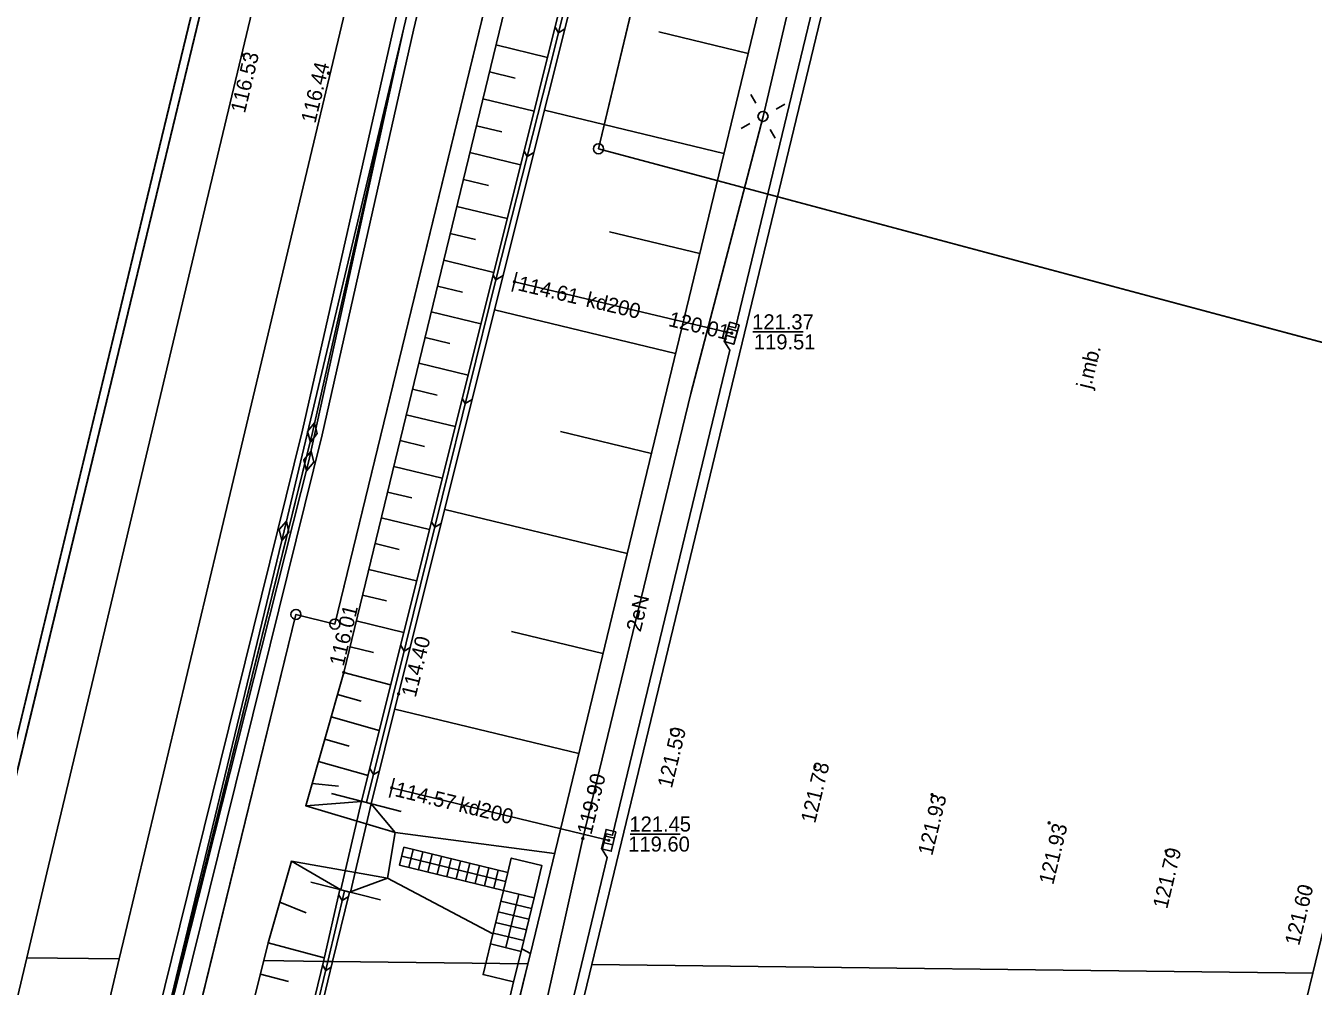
# Model space of a CAD drawing. Extents: x 6424617 to 6425697, y 5665845 to 5667190.
# Drawn here: x 6425319.6 to 6425383.8, y 5666563.1 to 5666611 of the extents above; entities that cross this region are included whole.
import ezdxf

# ---------------------------------------------------------------- set-up
doc = ezdxf.new("R2010")
doc.units = 0
for name, color, linetype in [('Warstwa 1', 7, 'Continuous'), ('Warstwa 10', 7, 'Continuous'), ('Warstwa 12', 7, 'Continuous'), ('Warstwa 13', 7, 'Continuous'), ('Warstwa 14', 7, 'Continuous'), ('Warstwa 15', 7, 'Continuous'), ('Warstwa 19', 7, 'Continuous'), ('Warstwa 2', 7, 'Continuous'), ('Warstwa 20', 7, 'Continuous'), ('Warstwa 21', 7, 'Continuous'), ('Warstwa 22', 7, 'Continuous'), ('Warstwa 25', 7, 'Continuous'), ('Warstwa 4', 7, 'Continuous'), ('Warstwa 47', 7, 'Continuous'), ('Warstwa 6', 7, 'Continuous'), ('Warstwa 61', 7, 'Continuous'), ('Warstwa 7', 7, 'Continuous'), ('Warstwa 8', 7, 'Continuous'), ('Warstwa 9', 7, 'Continuous')]:
    doc.layers.add(name, color=color, linetype=linetype)

msp = doc.modelspace()

# ---------------------------------------------------------------- linework, layer by layer
at = {"layer": 'Warstwa 1'}
for p, q in [((6425335.03, 5666581.17), (6425379.44, 5666763.67)), ((6425335.03, 5666581.17), (6425379.44, 5666763.67)), ((6425313.029, 5666550.146), (6425358.794, 5666739.45)), ((6425313.029, 5666550.146), (6425358.794, 5666739.45)), ((6425348.172, 5666604.865), (6425360.791, 5666657.874)), ((6425348.172, 5666604.865), (6425360.791, 5666657.874)), ((6425348.172, 5666604.865), (6425407.267, 5666589.052)), ((6425348.172, 5666604.865), (6425407.267, 5666589.052)), ((6425294.11, 5666422.45), (6425333.09, 5666581.65)), ((6425294.11, 5666422.45), (6425333.09, 5666581.65)), ((6425333.09, 5666581.65), (6425335.03, 5666581.17)), ((6425333.09, 5666581.65), (6425335.03, 5666581.17))]:
    msp.add_line(p, q, dxfattribs=at)
at = {"layer": 'Warstwa 10'}
for points in [[(6425353.93, 5666675.12), (6425353.26, 5666673.06), (6425338.47, 5666610.89)], [(6425338.47, 5666610.89), (6425332.5, 5666585.82)], [(6425338.47, 5666610.89), (6425333.91, 5666590.72)], [(6425333.91, 5666590.72), (6425327.399, 5666564.443)], [(6425332.5, 5666585.82), (6425327.338, 5666564.444)], [(6425334.86, 5666572.73), (6425338.33, 5666571.83)], [(6425333.83, 5666568.3), (6425337.3, 5666567.42)], [(6425327.338, 5666564.444), (6425324.99, 5666554.72), (6425317.35, 5666522.26), (6425310.45, 5666493.89), (6425307.494, 5666481.767)], [(6425327.447, 5666564.443), (6425324.99, 5666554.72)], [(6425324.99, 5666554.72), (6425327.399, 5666564.443)]]:
    msp.add_lwpolyline(points, dxfattribs=at)
for centre in [(6425348.172, 5666604.865), (6425333.09, 5666581.65), (6425335.03, 5666581.17)]:
    msp.add_circle(centre, 0.25, dxfattribs=at)
at = {"layer": 'Warstwa 12'}
for points in [[(6425371.5, 5666668.86), (6425368.61, 5666657.14), (6425364.68, 5666640.79), (6425360.52, 5666624.1), (6425356.37, 5666606.48), (6425352.78, 5666592.67), (6425347.39, 5666570.48), (6425345.993, 5666564.219)], [(6425343.98, 5666598.23), (6425354.56, 5666595.72), (6425354.81, 5666595.67)], [(6425337.87, 5666573.01), (6425348.44, 5666570.45), (6425348.68, 5666570.39)], [(6425339.14, 5666535.23), (6425344.13, 5666555.87), (6425345.993, 5666564.219)]]:
    msp.add_lwpolyline(points, dxfattribs=at)
at = {"layer": 'Warstwa 14'}
for p, q in [((6425358.364, 5666595.738), (6425355.863, 5666595.738)), ((6425352.245, 5666570.704), (6425349.744, 5666570.704))]:
    msp.add_line(p, q, dxfattribs=at)
for centre in [(6425343.98, 5666598.23), (6425354.56, 5666595.72), (6425354.81, 5666595.67), (6425337.87, 5666573.01), (6425347.39, 5666570.48), (6425348.68, 5666570.39)]:
    msp.add_circle(centre, 0.045, dxfattribs=at)
at = {"layer": 'Warstwa 19'}
for points in [[(6425333.808, 5666590.231), (6425334.155, 5666590.669), (6425334.012, 5666591.209), (6425333.665, 5666590.771)], [(6425333.609, 5666588.815), (6425333.973, 5666589.239), (6425333.851, 5666589.785), (6425333.487, 5666589.361)], [(6425332.378, 5666585.335), (6425332.742, 5666585.759), (6425332.622, 5666586.305), (6425332.258, 5666585.881)]]:
    msp.add_lwpolyline(points, close=True, dxfattribs=at)
at = {"layer": 'Warstwa 2'}
for points in [[(6425351.541, 5666814.161), (6425346.19, 5666783.6), (6425359.15, 5666739.31), (6425316.945, 5666564.569)], [(6425344.106, 5666562.008), (6425343.653, 5666562.12), (6425343.94, 5666563.332)]]:
    msp.add_lwpolyline(points, dxfattribs=at)
msp.add_circle((6425356.37, 5666606.48), 0.25, dxfattribs=at)
at = {"layer": 'Warstwa 20'}
for points in [[(6425404.522, 5666813.522), (6425404.196, 5666811.714), (6425403.132, 5666806.373), (6425401.821, 5666800.594), (6425391.249, 5666756.921), (6425390.59, 5666754.182), (6425344.776, 5666564.747), (6425344.652, 5666564.235)], [(6425338.043, 5666570.781), (6425333.575, 5666572.112), (6425335.476, 5666578.76), (6425340.458, 5666599.306), (6425345.009, 5666618.09), (6425349.685, 5666637.202), (6425354.713, 5666657.518), (6425359.407, 5666676.499), (6425364.317, 5666696.337), (6425370.582, 5666721.422), (6425376.359, 5666746.636), (6425378.933, 5666757.904), (6425380.111, 5666761.653), (6425384.025, 5666760.723)], [(6425331.487, 5666564.394), (6425331.711, 5666565.283), (6425332.875, 5666569.344), (6425337.651, 5666568.507)], [(6425306.496, 5666399.029), (6425311.317, 5666419.144), (6425338.808, 5666540.067), (6425344.652, 5666564.235)], [(6425307.315, 5666466.947), (6425307.814, 5666468.883), (6425314.453, 5666496.422), (6425321.245, 5666524.099), (6425327.788, 5666549.679), (6425331.487, 5666564.394)]]:
    msp.add_lwpolyline(points, dxfattribs=at)
at = {"layer": 'Warstwa 21'}
for p, q in [((6425344.095, 5666598.717), (6425343.865, 5666597.743)), ((6425337.988, 5666573.496), (6425337.752, 5666572.524))]:
    msp.add_line(p, q, dxfattribs=at)
for points in [[(6425334.917, 5666564.352), (6425335.752, 5666567.813), (6425337.651, 5666568.507), (6425338.043, 5666570.781), (6425336.841, 5666572.216), (6425338.207, 5666577.69), (6425353.108, 5666637.3), (6425362.223, 5666676.199), (6425366.904, 5666695.59), (6425372.943, 5666720.9), (6425378.889, 5666746.05), (6425381.38, 5666757.139), (6425382.211, 5666759.415), (6425384.025, 5666760.723), (6425384.533, 5666762.234), (6425383.43, 5666764.314), (6425384.167, 5666768.022), (6425388.16, 5666783.635), (6425394.548, 5666811.629), (6425394.925, 5666813.637)], [(6425382.211, 5666759.415), (6425381.594, 5666759.566), (6425380.892, 5666757.278), (6425378.411, 5666746.159), (6425372.465, 5666721.008), (6425366.426, 5666695.699), (6425361.745, 5666676.307), (6425352.63, 5666637.429), (6425337.729, 5666577.819), (6425336.364, 5666572.34), (6425336.841, 5666572.216)], [(6425335.752, 5666567.813), (6425335.269, 5666567.935), (6425334.457, 5666564.358)], [(6425307.108, 5666449.766), (6425311.778, 5666468.481), (6425334.917, 5666564.352)], [(6425334.457, 5666564.358), (6425324.684, 5666524.027), (6425311.3, 5666468.61), (6425307.134, 5666451.915)]]:
    msp.add_lwpolyline(points, dxfattribs=at)
at = {"layer": 'Warstwa 22'}
msp.add_lwpolyline([(6425336.356, 5666572.342), (6425336.839, 5666572.217), (6425335.805, 5666567.799), (6425335.321, 5666567.922)], close=True, dxfattribs=at)
at = {"layer": 'Warstwa 25'}
for centre in [(6425330.459, 5666609.53), (6425334.715, 5666608.633), (6425335.476, 5666578.76), (6425338.207, 5666577.69), (6425351.799, 5666575.894), (6425358.959, 5666574.074), (6425364.795, 5666572.668), (6425370.632, 5666571.263), (6425376.458, 5666569.847), (6425383.537, 5666568.018)]:
    msp.add_circle(centre, 0.045, dxfattribs=at)
at = {"layer": 'Warstwa 4'}
for p, q in [((6425355.002, 5666595.433), (6425354.521, 5666595.571)), ((6425355.099, 5666595.769), (6425354.618, 5666595.907)), ((6425348.963, 5666570.503), (6425348.477, 5666570.618)), ((6425348.883, 5666570.162), (6425348.397, 5666570.277))]:
    msp.add_line(p, q, dxfattribs=at)
for points in [[(6425356.007, 5666607.136), (6425355.765, 5666607.574)], [(6425357.026, 5666606.843), (6425357.464, 5666607.085)], [(6425355.714, 5666606.117), (6425355.276, 5666605.875)], [(6425356.733, 5666605.824), (6425356.975, 5666605.386)]]:
    msp.add_lwpolyline(points, dxfattribs=at)
for points in [[(6425355.189, 5666596.081), (6425354.912, 5666595.12), (6425354.431, 5666595.259), (6425354.708, 5666596.22)], [(6425349.038, 5666570.819), (6425348.809, 5666569.846), (6425348.322, 5666569.961), (6425348.551, 5666570.934)]]:
    msp.add_lwpolyline(points, close=True, dxfattribs=at)
at = {"layer": 'Warstwa 47'}
for points in [[(6425404.522, 5666813.522), (6425404.196, 5666811.714), (6425403.132, 5666806.373), (6425401.821, 5666800.594), (6425391.249, 5666756.921), (6425390.59, 5666754.182), (6425344.776, 5666564.747), (6425344.652, 5666564.235)], [(6425344.651, 5666564.235), (6425344.106, 5666562.008), (6425311.317, 5666419.144), (6425306.496, 5666399.029)]]:
    msp.add_lwpolyline(points, dxfattribs=at)
at = {"layer": 'Warstwa 6'}
for points in [[(6425358.794, 5666739.45), (6425345.837, 5666783.728), (6425348.185, 5666793.45), (6425355.292, 5666837.846), (6425290.369, 5666852.842), (6425257.3, 5666717.295), (6425256.529, 5666713.915), (6425237.206, 5666634.214), (6425213.474, 5666536.345), (6425279.567, 5666529.498), (6425296.119, 5666527.878), (6425306.817, 5666551.711), (6425313.029, 5666550.146)], [(6425360.791, 5666657.874), (6425348.172, 5666604.865), (6425407.267, 5666589.052), (6425420.309, 5666643.115)]]:
    msp.add_lwpolyline(points, close=True, dxfattribs=at)
for points in [[(6425244.275, 5666264.977), (6425279.037, 5666410.906), (6425312.219, 5666546.795), (6425313.029, 5666550.146), (6425358.794, 5666739.45), (6425345.837, 5666783.728), (6425348.185, 5666793.45), (6425355.292, 5666837.846), (6425351.457, 5666842.463), (6425355.995, 5666841.398), (6425356.96, 5666840.82), (6425392.62, 5666819.33), (6425392.36, 5666816.84), (6425379.44, 5666763.67), (6425335.03, 5666581.17), (6425333.09, 5666581.65), (6425294.11, 5666422.45), (6425272.8, 5666335.34)], [(6425353.441, 5666367.596), (6425363.818, 5666408.694), (6425377.52, 5666465.123), (6425381.456, 5666483.847), (6425392.009, 5666527.133), (6425393.198, 5666530.378), (6425400.851, 5666561.248), (6425407.267, 5666589.052), (6425348.172, 5666604.865), (6425360.791, 5666657.874), (6425420.309, 5666643.115), (6425424.332, 5666659.157), (6425447.915, 5666756.464), (6425449.817, 5666764.101), (6425450.35, 5666766.844), (6425453.13, 5666778.441), (6425454.155, 5666782.149), (6425437.407, 5666792.342), (6425392.62, 5666819.33)], [(6425392.36, 5666816.84), (6425379.44, 5666763.67), (6425335.03, 5666581.17), (6425333.09, 5666581.65), (6425294.11, 5666422.45), (6425272.8, 5666335.34)], [(6425347.315, 5666564.203), (6425348.603, 5666569.53), (6425348.351, 5666569.934), (6425348.545, 5666570.721), (6425348.874, 5666570.645), (6425354.722, 5666594.817), (6425354.469, 5666595.222), (6425354.653, 5666596.019), (6425354.992, 5666595.933), (6425359.424, 5666614.259)], [(6425306.368, 5666388.415), (6425311.528, 5666409.747), (6425311.275, 5666410.152), (6425311.459, 5666410.938), (6425311.798, 5666410.862), (6425324.365, 5666464.253), (6425324.113, 5666464.668), (6425324.297, 5666465.454), (6425324.626, 5666465.379), (6425330.531, 5666491.58), (6425330.278, 5666491.995), (6425330.472, 5666492.782), (6425330.801, 5666492.706), (6425336.716, 5666518.898), (6425336.453, 5666519.323), (6425336.638, 5666520.11), (6425336.966, 5666520.034), (6425342.505, 5666544.261), (6425342.253, 5666544.676), (6425342.437, 5666545.463), (6425342.766, 5666545.387), (6425347.315, 5666564.203)]]:
    msp.add_lwpolyline(points, dxfattribs=at)
at = {"layer": 'Warstwa 61'}
for points in [[(6425365.002, 5666813.999), (6425364.967, 5666813.872), (6425361.084, 5666799.763), (6425361.077, 5666799.738), (6425357.8, 5666784.86), (6425359.44, 5666776.98), (6425364.19, 5666763.93), (6425367.97, 5666751.39), (6425368.86, 5666745.46), (6425368.53, 5666739.28), (6425366.74, 5666730.22), (6425362.21, 5666711.06), (6425358.59, 5666696.28), (6425353.93, 5666675.12), (6425353.26, 5666673.06), (6425338.47, 5666610.89), (6425333.911, 5666590.725), (6425333.909, 5666590.715), (6425327.427, 5666564.557), (6425327.399, 5666564.443)], [(6425338.361, 5666569.595), (6425343.54, 5666568.341)], [(6425344.195, 5666567.708), (6425343.552, 5666565.04)], [(6425327.399, 5666564.443), (6425307.494, 5666481.768)]]:
    msp.add_lwpolyline(points, dxfattribs=at)
at = {"layer": 'Warstwa 7'}
for points in [[(6425338.469, 5666570.043), (6425343.648, 5666568.789), (6425343.821, 5666569.506), (6425345.345, 5666569.138), (6425344.958, 5666567.524), (6425343.432, 5666567.892), (6425338.253, 5666569.146)], [(6425343.432, 5666567.892), (6425342.785, 5666565.225), (6425342.416, 5666563.699), (6425343.94, 5666563.332), (6425344.318, 5666564.855), (6425344.958, 5666567.524)]]:
    msp.add_lwpolyline(points, close=True, dxfattribs=at)
for points in [[(6425338.94, 5666569.929), (6425338.724, 5666569.032)], [(6425339.411, 5666569.815), (6425339.195, 5666568.918)], [(6425339.881, 5666569.701), (6425339.665, 5666568.804)], [(6425340.352, 5666569.587), (6425340.136, 5666568.69)], [(6425340.823, 5666569.473), (6425340.607, 5666568.576)], [(6425341.294, 5666569.359), (6425341.078, 5666568.462)], [(6425341.765, 5666569.245), (6425341.549, 5666568.348)], [(6425342.236, 5666569.131), (6425342.02, 5666568.234)], [(6425342.706, 5666569.017), (6425342.49, 5666568.12)], [(6425343.177, 5666568.903), (6425342.961, 5666568.006)], [(6425343.648, 5666568.789), (6425343.432, 5666567.892)], [(6425343.303, 5666567.359), (6425344.83, 5666566.99)], [(6425343.173, 5666566.825), (6425344.702, 5666566.456)], [(6425343.044, 5666566.292), (6425344.574, 5666565.923)], [(6425342.785, 5666565.225), (6425344.318, 5666564.855)], [(6425342.914, 5666565.758), (6425344.446, 5666565.389)]]:
    msp.add_lwpolyline(points, dxfattribs=at)
at = {"layer": 'Warstwa 8'}
for p, q in [((6425347.831, 5666564.197), (6425400.917, 5666783.785)), ((6425383.772, 5666563.763), (6425403.546, 5666645.693)), ((6425328.55, 5666601.862), (6425331.332, 5666613.536)), ((6425332.933, 5666600.813), (6425335.715, 5666612.486)), ((6425325.314, 5666588.236), (6425328.55, 5666601.862)), ((6425329.231, 5666585.244), (6425332.933, 5666600.813)), ((6425322.997, 5666578.505), (6425325.314, 5666588.236)), ((6425324.598, 5666565.792), (6425329.231, 5666585.244)), ((6425320.681, 5666568.773), (6425322.997, 5666578.505)), ((6425319.672, 5666564.536), (6425320.681, 5666568.773)), ((6425324.286, 5666564.481), (6425324.598, 5666565.792)), ((6425316.719, 5666552.14), (6425319.672, 5666564.536)), ((6425319.672, 5666564.536), (6425324.286, 5666564.481)), ((6425319.672, 5666564.536), (6425324.286, 5666564.481)), ((6425319.965, 5666546.329), (6425324.286, 5666564.481)), ((6425342.162, 5666540.747), (6425347.831, 5666564.197)), ((6425347.831, 5666564.197), (6425383.772, 5666563.763)), ((6425347.831, 5666564.197), (6425383.772, 5666563.763)), ((6425377.625, 5666538.377), (6425383.772, 5666563.763))]:
    msp.add_line(p, q, dxfattribs=at)
for points in [[(6425365.519, 5666813.992), (6425364.485, 5666814.005), (6425360.594, 5666799.87), (6425357.289, 5666784.863), (6425358.958, 5666776.843), (6425363.715, 5666763.772), (6425367.481, 5666751.28), (6425368.358, 5666745.436), (6425368.033, 5666739.342), (6425366.251, 5666730.326), (6425361.724, 5666711.177), (6425358.103, 5666696.393), (6425353.447, 5666675.251), (6425352.778, 5666673.195), (6425337.983, 5666611.003), (6425333.423, 5666590.835), (6425326.886, 5666564.449)], [(6425327.912, 5666564.437), (6425334.397, 5666590.605), (6425338.957, 5666610.777), (6425353.742, 5666672.925), (6425354.413, 5666674.989), (6425359.077, 5666696.167), (6425362.696, 5666710.943), (6425367.229, 5666730.114), (6425369.027, 5666739.218), (6425369.362, 5666745.484), (6425368.459, 5666751.5), (6425364.665, 5666764.088), (6425359.922, 5666777.117), (6425358.311, 5666784.857), (6425361.566, 5666799.63), (6425365.519, 5666813.992)], [(6425338.47, 5666610.89), (6425333.73, 5666589.3)], [(6425333.73, 5666589.3), (6425327.447, 5666564.443)], [(6425307.467, 5666479.546), (6425310.936, 5666493.772), (6425317.836, 5666522.144), (6425325.476, 5666554.603), (6425327.912, 5666564.437)], [(6425307.521, 5666483.988), (6425309.964, 5666494.008), (6425316.864, 5666522.376), (6425324.504, 5666554.837), (6425326.886, 5666564.449)]]:
    msp.add_lwpolyline(points, dxfattribs=at)
at = {"layer": 'Warstwa 9'}
for p, q in [((6425316.945, 5666564.569), (6425359.15, 5666739.31)), ((6425345.664, 5666608.594), (6425348.2, 5666618.817)), ((6425346.004, 5666610.923), (6425346.172, 5666610.644)), ((6425346.493, 5666610.838), (6425346.172, 5666610.644)), ((6425355.626, 5666609.613), (6425351.176, 5666610.69)), ((6425343.059, 5666610.04), (6425345.628, 5666609.419)), ((6425342.734, 5666608.698), (6425344.013, 5666608.388)), ((6425343.07, 5666598.39), (6425345.664, 5666608.594)), ((6425342.408, 5666607.356), (6425344.958, 5666606.739)), ((6425354.421, 5666604.628), (6425345.481, 5666606.791)), ((6425342.083, 5666606.014), (6425343.353, 5666605.707)), ((6425341.758, 5666604.673), (6425344.289, 5666604.061)), ((6425344.461, 5666604.751), (6425344.619, 5666604.485)), ((6425344.955, 5666604.685), (6425344.619, 5666604.485)), ((6425341.433, 5666603.331), (6425342.694, 5666603.026)), ((6425341.108, 5666601.989), (6425343.619, 5666601.382)), ((6425340.783, 5666600.648), (6425342.034, 5666600.344)), ((6425353.216, 5666599.643), (6425348.726, 5666600.729)), ((6425340.458, 5666599.306), (6425342.949, 5666598.701)), ((6425342.914, 5666598.561), (6425343.055, 5666598.329)), ((6425340.147, 5666598.022), (6425341.388, 5666597.721)), ((6425340.38, 5666587.499), (6425343.07, 5666598.39)), ((6425343.422, 5666598.551), (6425343.055, 5666598.329)), ((6425339.835, 5666596.738), (6425342.308, 5666596.139)), ((6425352.01, 5666594.658), (6425342.994, 5666596.839)), ((6425339.524, 5666595.454), (6425340.756, 5666595.156)), ((6425339.212, 5666594.17), (6425341.668, 5666593.575)), ((6425338.901, 5666592.886), (6425340.124, 5666592.589)), ((6425341.378, 5666592.416), (6425341.532, 5666592.162)), ((6425341.877, 5666592.37), (6425341.532, 5666592.162)), ((6425338.59, 5666591.601), (6425341.027, 5666591.011)), ((6425338.278, 5666590.317), (6425339.492, 5666590.023)), ((6425350.804, 5666589.673), (6425346.277, 5666590.768)), ((6425337.967, 5666589.033), (6425340.386, 5666588.447)), ((6425337.656, 5666587.749), (6425338.86, 5666587.457)), ((6425338.587, 5666580.232), (6425340.38, 5666587.499)), ((6425337.344, 5666586.465), (6425339.745, 5666585.883)), ((6425349.599, 5666584.688), (6425340.506, 5666586.888)), ((6425339.842, 5666586.272), (6425340.009, 5666585.995)), ((6425340.332, 5666586.19), (6425340.009, 5666585.995)), ((6425337.033, 5666585.18), (6425338.229, 5666584.891)), ((6425336.722, 5666583.896), (6425339.104, 5666583.32)), ((6425336.41, 5666582.612), (6425337.597, 5666582.325)), ((6425336.099, 5666581.328), (6425338.463, 5666580.755)), ((6425348.393, 5666579.703), (6425343.828, 5666580.807)), ((6425335.788, 5666580.044), (6425336.962, 5666579.747)), ((6425336.603, 5666572.278), (6425338.587, 5666580.232)), ((6425338.306, 5666580.128), (6425338.487, 5666579.828)), ((6425338.787, 5666580.008), (6425338.487, 5666579.828)), ((6425335.476, 5666578.76), (6425337.81, 5666578.144)), ((6425335.159, 5666577.652), (6425336.342, 5666577.327)), ((6425347.187, 5666574.717), (6425338.019, 5666576.935)), ((6425334.842, 5666576.544), (6425337.241, 5666575.859)), ((6425334.526, 5666575.436), (6425335.744, 5666575.088)), ((6425334.209, 5666574.328), (6425336.684, 5666573.621)), ((6425336.769, 5666573.965), (6425336.949, 5666573.665)), ((6425337.247, 5666573.844), (6425336.949, 5666573.665)), ((6425333.892, 5666573.22), (6425335.207, 5666573.096)), ((6425333.575, 5666572.112), (6425336.36, 5666572.322)), ((6425332.875, 5666569.344), (6425335.321, 5666567.922)), ((6425337.651, 5666568.507), (6425342.908, 5666565.733)), ((6425334.687, 5666564.355), (6425335.511, 5666567.874)), ((6425332.293, 5666567.314), (6425333.602, 5666566.77)), ((6425335.213, 5666567.686), (6425335.397, 5666567.389)), ((6425335.694, 5666567.573), (6425335.397, 5666567.389)), ((6425331.711, 5666565.283), (6425334.5, 5666564.532)), ((6425344.346, 5666564.974), (6425344.776, 5666564.747)), ((6425330.974, 5666548.963), (6425334.687, 5666564.355)), ((6425334.414, 5666564.179), (6425334.579, 5666563.908)), ((6425334.85, 5666564.073), (6425334.579, 5666563.908)), ((6425331.318, 5666563.722), (6425332.723, 5666563.357))]:
    msp.add_line(p, q, dxfattribs=at)
for points in [[(6425336.364, 5666572.34), (6425336.841, 5666572.216), (6425338.207, 5666577.69), (6425353.108, 5666637.3), (6425362.223, 5666676.199), (6425366.904, 5666695.59), (6425372.943, 5666720.9), (6425378.889, 5666746.05), (6425381.38, 5666757.139), (6425382.211, 5666759.415), (6425381.594, 5666759.566), (6425380.892, 5666757.278), (6425378.411, 5666746.159), (6425372.465, 5666721.008), (6425366.426, 5666695.699), (6425361.745, 5666676.307), (6425352.63, 5666637.429), (6425337.729, 5666577.819)], [(6425337.651, 5666568.507), (6425335.752, 5666567.813), (6425335.269, 5666567.935), (6425334.457, 5666564.358), (6425331.487, 5666564.394), (6425331.711, 5666565.283), (6425332.875, 5666569.344)], [(6425334.457, 5666564.358), (6425335.269, 5666567.935), (6425335.752, 5666567.813), (6425334.917, 5666564.352)], [(6425306.496, 5666399.029), (6425311.317, 5666419.144), (6425338.808, 5666540.067), (6425344.652, 5666564.235), (6425334.917, 5666564.352), (6425311.778, 5666468.481), (6425307.108, 5666449.766)], [(6425307.108, 5666449.766), (6425311.778, 5666468.481), (6425334.917, 5666564.352), (6425334.457, 5666564.358), (6425324.684, 5666524.027), (6425311.3, 5666468.61), (6425307.134, 5666451.915)], [(6425334.457, 5666564.358), (6425324.684, 5666524.027), (6425311.3, 5666468.61), (6425307.134, 5666451.915), (6425307.315, 5666466.947), (6425307.814, 5666468.883), (6425314.453, 5666496.422), (6425321.245, 5666524.099), (6425327.788, 5666549.679), (6425331.487, 5666564.394)]]:
    msp.add_lwpolyline(points, close=True, dxfattribs=at)
for points in [[(6425390.59, 5666754.182), (6425344.776, 5666564.747), (6425344.652, 5666564.235), (6425334.917, 5666564.352), (6425335.752, 5666567.813), (6425337.651, 5666568.507), (6425338.043, 5666570.781), (6425336.841, 5666572.216), (6425338.207, 5666577.69), (6425353.108, 5666637.3), (6425362.223, 5666676.199)], [(6425361.745, 5666676.307), (6425352.63, 5666637.429), (6425337.729, 5666577.819), (6425336.364, 5666572.34), (6425336.841, 5666572.216), (6425338.043, 5666570.781), (6425333.575, 5666572.112), (6425335.476, 5666578.76), (6425340.458, 5666599.306), (6425345.009, 5666618.09), (6425349.685, 5666637.202), (6425354.713, 5666657.518), (6425359.407, 5666676.499)], [(6425338.043, 5666570.781), (6425336.838, 5666572.203)], [(6425345.982, 5666569.732), (6425338.043, 5666570.781)]]:
    msp.add_lwpolyline(points, dxfattribs=at)

# ---------------------------------------------------------------- texts
at = {"layer": 'Warstwa 13'}
for s, rotation, p in [('kd200', 346.65665, (6425347.502, 5666597.009)), ('2eN', 76.34663, (6425350.27, 5666580.745)), ('kd200', 346.38736, (6425341.156, 5666571.828))]:
    msp.add_text(s, height=0.75, rotation=rotation, dxfattribs=at).set_placement(p)
at = {"layer": 'Warstwa 14'}
for s, rotation, p in [('114.61', 346.65665, (6425344.105, 5666597.814)), ('120.01', 346.65665, (6425351.615, 5666596.034)), ('119.90', 76.34663, (6425347.813, 5666570.633)), ('114.57', 346.38736, (6425337.979, 5666572.598))]:
    msp.add_text(s, height=0.75, rotation=rotation, dxfattribs=at).set_placement(p)
for s, p in [('119.51', (6425355.917, 5666594.863)), ('119.60', (6425349.654, 5666569.829))]:
    msp.add_text(s, height=0.75, dxfattribs=at).set_placement(p)
at = {"layer": 'Warstwa 15'}
for s, p in [('121.37', (6425355.831, 5666595.863)), ('121.45', (6425349.712, 5666570.829))]:
    msp.add_text(s, height=0.75, dxfattribs=at).set_placement(p)
at = {"layer": 'Warstwa 25'}
for s, rotation, p in [('116.53', 76.59873, (6425330.546, 5666606.603)), ('116.44', 76.593, (6425334.057, 5666606.097)), ('116.01', 76.36954, (6425335.467, 5666579.032)), ('114.40', 75.96274, (6425339.056, 5666577.478)), ('121.59', 76.40965, (6425351.825, 5666572.952)), ('121.78', 76.40965, (6425358.968, 5666571.205)), ('121.93', 76.34663, (6425364.803, 5666569.592)), ('121.93', 76.43257, (6425370.834, 5666568.142)), ('121.79', 76.43257, (6425376.512, 5666566.936)), ('121.60', 76.43257, (6425383.092, 5666565.104))]:
    msp.add_text(s, height=0.75, rotation=rotation, dxfattribs=at).set_placement(p)
at = {"layer": 'Warstwa 8'}
msp.add_text('j.mb.', height=0.75, rotation=76.43257, dxfattribs=at).set_placement((6425372.709, 5666592.859))

doc.saveas('drawing.dxf')
